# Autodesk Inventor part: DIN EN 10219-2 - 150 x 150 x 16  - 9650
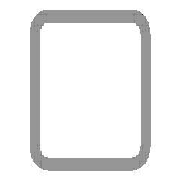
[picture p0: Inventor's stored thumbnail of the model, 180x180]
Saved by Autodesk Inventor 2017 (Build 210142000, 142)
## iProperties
IsCustomPart: 1
Created: 2017-11
Part Number: DIN EN 10219-2 - 150 x 150 x 16  - 9650
Material: Steel, Mild
Description: Cold formed welded structural hollow sections of non-alloy and fine grain structural steel
Document SubType Name: Modeling
Standard: DIN
Designer: iusti
Standard Revision: 2006-07
Standards Organization: DIN
Language: en-US
Size Designation: 150 x 150 x 16
Categories: <MemberInstance><Categories><Category DisplayName="Structural Shapes" InternalName="089c4875-fa83-4c05-b084-43b9cc11f5ed" Mnemonic="GRDR"><CategoryParameter Dis
Stock Number: 150 x 150 x 16
Density: 7.85 g/cm^3
Appearance: Semi-Polished
Mass: 557615 g
Surface Area: 89003.7 cm^2
Volume: 71033.8 cm^3
_CCFamilyMember: 76
_CCFamilyDisplayName: DIN EN 10219-2 (Square Hollow Section - Cold Formed) - Cold formed welded structural hollow sections of non-alloy and fine grain structural steel
_FrameMemberDoc: Frame Member File
_Version: 15.0.0
_GetPNFromCC: 1
G_L: 9650.000 mm
G_W: 150.000 mm
G_H: 150.000 mm
+A69F4663-CFB7-4D18-824B-3D97B0B5E8F0+CUTDETAIL1: Cut
+26595D0A-3E89-4A2F-9DA7-6BDC5E0BE6FD+CUTDETAIL2: Cut
+81F2769D-CBCB-4BAE-9991-99821565208A+CUTDETAIL3: Miter 45.00 deg
+B125B8ED-1570-405A-A825-64B3EFBC6DC3+CUTDETAIL4: Miter 45.00 deg
Author: iusti
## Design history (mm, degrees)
node "Start plane"
node "End plane"
sketch "Sketch"
  geometry: L1 (-75, -27)-(-75, 27); L2 (-27, 75)-(27, 75); L3 (75, 27)-(75, -27); L4 (27, -75)-(-27, -75); L5 (-27, 59)-(27, 59); L6 (59, 27)-(59, -27); L7 (27, -59)-(-27, -59); L8 (-59, -27)-(-59, 27); L9 (0, 118.918)-(0, -118.918) reference; L10 (-118.918, 0)-(118.918, 0) reference; A1 r 48 centre (-27, -27) between (-75, -27) and (-27, -75); A2 r 48 centre (-27, 27) between (-27, 75) and (-75, 27); A3 r 48 centre (27, 27) between (75, 27) and (27, 75); A4 r 48 centre (27, -27) between (27, -75) and (75, -27); A5 r 32 centre (-27, 27) between (-27, 59) and (-59, 27); A6 r 32 centre (27, 27) between (59, 27) and (27, 59); A7 r 32 centre (27, -27) between (27, -59) and (59, -27); A8 r 32 centre (-27, -27) between (-59, -27) and (-27, -59)
  constraints: 16 end point, 16 point on circle, 8 centre point, 8 tangent, 4 parallel, 3 equal radius, 2 perpendicular, 7 other
  dimensions: "d7" = 48 radius of A1 (= G_IR); "d10" = 150 distance between parallel lines of L2 L4 (= G_H); "d11" = 150 distance between parallel lines of L1 L3 (= G_W); "d12" = 16 distance between parallel lines of L3 L6 (= G_T); "d15" = 75 distance between parallel lines of L2 L10 (= 0.5 x d10); "d16" = 75 distance between parallel lines of L9 L3 (= 0.5 x d11)
extrude "Body" new body sketch "Sketch" stored distance "d3" = 9650 (= G_L); taper "d4" = 0 deg
node "Driven Length"
  sketch "Sketch3"
    geometry: L1 (0, 0)-(10, 0) reference
    constraints: 2 end point, 1 horizontal
  workplane "Work Plane3"
  sketch "Sketch4"
    geometry: L1 (-2, -75)-(12, -75) reference; L2 (-2, 9575)-(12, 9575) reference
    dimensions: "d18" = 9650 distance between parallel lines of L1 L2 (derived)
workplane "Work Plane4"
split "Split1"
workplane "Work Plane5"
split "Split2"
workplane "Work Plane6"
split "Split3"
workplane "Work Plane7"
split "Split4"
body "Solid1"
other parameters: "G_W" = 150 [user parameter; used in 1 equation term], "G_H" = 150 [user parameter; used in 1 equation term], "G_T" = 16 [user parameter; used in 1 equation term], "G_IR" = 48 [user parameter; used in 1 equation term], "G_L" = 9650 (= d18) [user parameter; used in 1 equation term], "G_OFFSET_START" = 75 [user parameter; used in 1 equation term], "G_OFFSET_END" = 75 [user parameter; used in 1 equation term], "d13" = -75 (= -G_OFFSET_START), "d14" = 9575 (= G_OFFSET_END + B_L), "d17" = 90 deg
